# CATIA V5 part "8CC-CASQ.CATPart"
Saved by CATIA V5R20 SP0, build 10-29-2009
Part number: 8CC-CASQ
Revision: ANY
Definition: UNKNOWN
Nomenclature: 8CC-CASQ
Source: Unknown
Bounding box of the stored display mesh (mm): x -1.525 to 1.525, y -1.525 to 1.525, z 0 to 3
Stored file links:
  C:\Users\Utente\Desktop\IO LAVORO\3D X SITO CF\CUMSA\3D files CC\CCHS5328\8CC-CASQ.CATPart
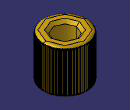
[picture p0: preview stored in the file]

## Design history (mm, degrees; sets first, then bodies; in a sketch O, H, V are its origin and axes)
Body1 "Cortar-Extruir2" (main body)
  Solid1: solid without history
